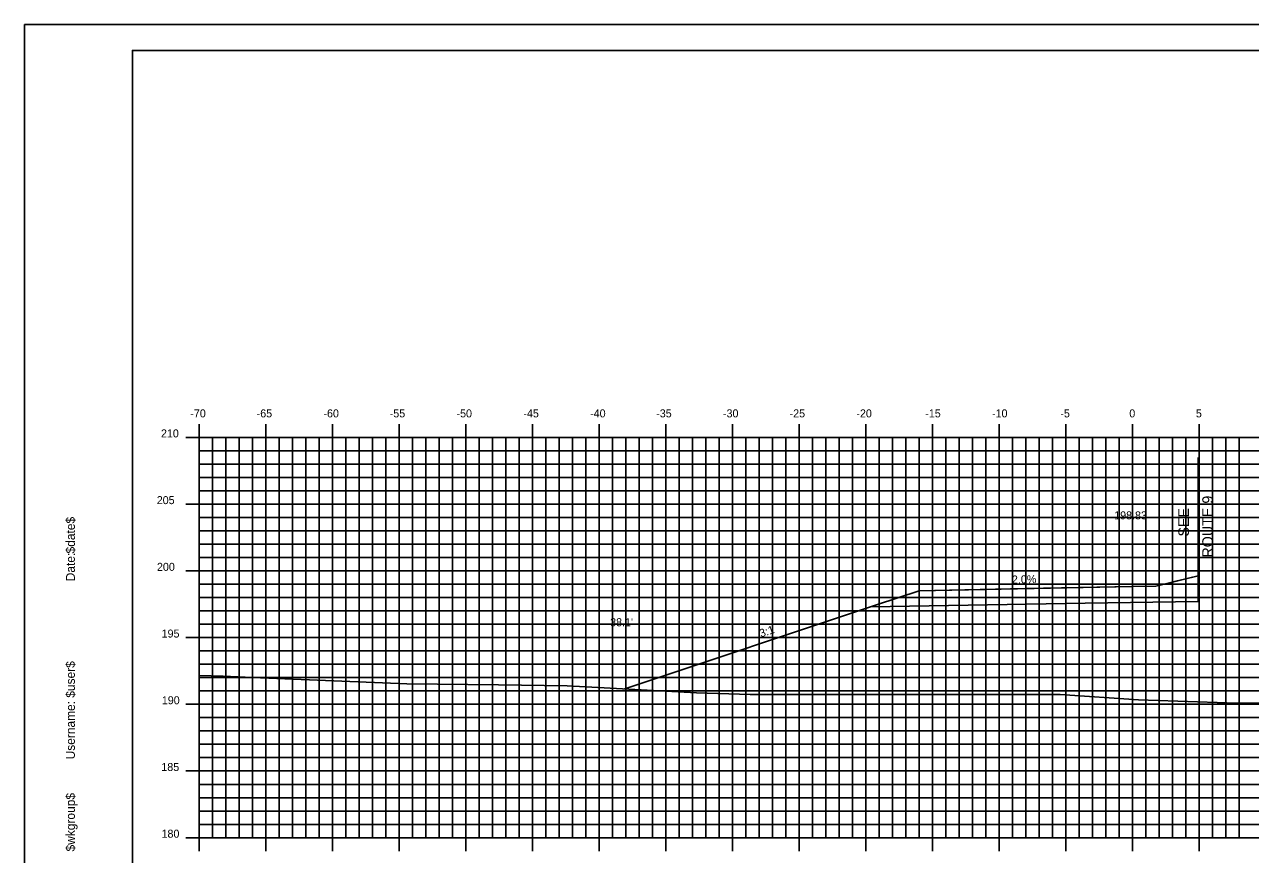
# Model space of a CAD drawing. Extents: x 1723321 to 1723493, y 458501 to 458611.
# Drawn here: x 1723320.9 to 1723412.9, y 458549 to 458611.2 of the extents above; entities that cross this region are included whole.
import ezdxf

# ---------------------------------------------------------------- set-up
doc = ezdxf.new("R2010")
doc.units = 0
for name, color, linetype in [('ANNOTATION', 7, 'Continuous'), ('BORDER', 7, 'Continuous'), ('D_Roadway_Centerline', 7, 'Continuous'), ('D_Roadway_Centerline_Text', 7, 'Continuous'), ('D_Roadway_Edge_Shoulder', 7, 'Continuous'), ('D_Roadway_SlopeLines', 7, 'Continuous'), ('D_Roadway_SubGrade', 7, 'Continuous'), ('D_Text_Standard', 7, 'Continuous'), ('H_V ANNOTATION', 7, 'Continuous'), ('MAJOR', 7, 'Continuous'), ('MINOR', 7, 'Continuous'), ('PLOT BOUNDARY', 7, 'Continuous'), ('S_Roadway_Centerline', 7, 'Continuous')]:
    doc.layers.add(name, color=color, linetype=linetype)

msp = doc.modelspace()

# ---------------------------------------------------------------- linework, layer by layer
msp.add_lwpolyline([(1723365.961, 458561.403), (1723384.837, 458567.696), (1723388.029, 458568.759), (1723396.029, 458568.919), (1723404.029, 458569.079), (1723405.784, 458569.114)])
at = {"layer": 'ANNOTATION'}
msp.add_line((1723400.476, 458567.821), (1723384.391, 458567.547), dxfattribs=at)
at = {"layer": 'BORDER'}
msp.add_lwpolyline([(1723329.029, 458504.254), (1723489.029, 458504.254), (1723489.029, 458609.254), (1723329.029, 458609.254)], close=True, dxfattribs=at)
at = {"layer": 'D_Roadway_Centerline'}
msp.add_lwpolyline([(1723405.784, 458569.114), (1723406.719, 458569.342), (1723407.412, 458569.511), (1723408.964, 458569.889)], dxfattribs=at)
at = {"layer": 'D_Roadway_Edge_Shoulder'}
msp.add_line((1723408.964, 458569.889), (1723408.964, 458569.639), dxfattribs=at)
msp.add_line((1723408.964, 458569.889), (1723408.964, 458569.639), dxfattribs=at)
at = {"layer": 'D_Roadway_SlopeLines'}
msp.add_line((1723388.029, 458568.759), (1723404.029, 458569.079), dxfattribs=at)
for points in [[(1723408.964, 458569.889), (1723405.784, 458569.114)], [(1723408.964, 458569.889), (1723405.784, 458569.114)], [(1723408.964, 458569.889), (1723405.784, 458569.114)], [(1723408.964, 458569.889), (1723405.784, 458569.114)], [(1723408.964, 458569.889), (1723405.784, 458569.114)], [(1723408.964, 458569.889), (1723405.784, 458569.114)], [(1723408.964, 458569.889), (1723405.784, 458569.114)], [(1723408.964, 458569.889), (1723405.784, 458569.114)], [(1723408.964, 458569.889), (1723405.784, 458569.114)], [(1723404.029, 458569.079), (1723405.784, 458569.114)], [(1723388.029, 458568.759), (1723384.837, 458567.696), (1723365.961, 458561.403)]]:
    msp.add_lwpolyline(points, dxfattribs=at)
at = {"layer": 'D_Roadway_SubGrade'}
msp.add_line((1723408.964, 458578.748), (1723408.964, 458567.966), dxfattribs=at)
for points in [[(1723405.784, 458569.114), (1723408.964, 458569.889), (1723408.964, 458569.639)], [(1723405.784, 458569.114), (1723408.964, 458569.889), (1723408.964, 458569.639)], [(1723405.784, 458569.114), (1723408.964, 458569.889), (1723408.964, 458569.639)], [(1723408.964, 458569.639), (1723408.964, 458569.889), (1723405.784, 458569.114)], [(1723400.476, 458567.821), (1723408.964, 458567.966)], [(1723408.964, 458567.966), (1723400.476, 458567.821)], [(1723408.964, 458567.966), (1723400.476, 458567.821)], [(1723408.964, 458567.966), (1723400.476, 458567.821)]]:
    msp.add_lwpolyline(points, dxfattribs=at)
at = {"layer": 'MAJOR'}
for p, q in [((1723334.029, 458581.256), (1723334.029, 458580.254)), ((1723339.029, 458581.256), (1723339.029, 458580.254)), ((1723344.029, 458581.256), (1723344.029, 458580.254)), ((1723349.029, 458581.256), (1723349.029, 458580.254)), ((1723354.029, 458581.256), (1723354.029, 458580.254)), ((1723359.029, 458581.256), (1723359.029, 458580.254)), ((1723364.029, 458581.256), (1723364.029, 458580.254)), ((1723369.029, 458581.256), (1723369.029, 458580.254)), ((1723374.029, 458581.256), (1723374.029, 458580.254)), ((1723379.029, 458581.256), (1723379.029, 458580.254)), ((1723384.029, 458581.256), (1723384.029, 458580.254)), ((1723389.029, 458581.256), (1723389.029, 458580.254)), ((1723394.029, 458581.256), (1723394.029, 458580.254)), ((1723399.029, 458581.256), (1723399.029, 458580.254)), ((1723404.029, 458581.256), (1723404.029, 458580.254)), ((1723409.029, 458581.256), (1723409.029, 458580.254)), ((1723333.027, 458580.254), (1723334.029, 458580.254)), ((1723334.029, 458580.254), (1723474.029, 458580.254)), ((1723334.029, 458550.254), (1723334.029, 458580.254)), ((1723334.029, 458550.254), (1723334.029, 458580.254)), ((1723334.029, 458580.254), (1723474.029, 458580.254)), ((1723339.029, 458550.254), (1723339.029, 458580.254)), ((1723344.029, 458550.254), (1723344.029, 458580.254)), ((1723349.029, 458550.254), (1723349.029, 458580.254)), ((1723354.029, 458550.254), (1723354.029, 458580.254)), ((1723359.029, 458550.254), (1723359.029, 458580.254)), ((1723364.029, 458550.254), (1723364.029, 458580.254)), ((1723369.029, 458550.254), (1723369.029, 458580.254)), ((1723374.029, 458550.254), (1723374.029, 458580.254)), ((1723379.029, 458550.254), (1723379.029, 458580.254)), ((1723384.029, 458550.254), (1723384.029, 458580.254)), ((1723389.029, 458550.254), (1723389.029, 458580.254)), ((1723394.029, 458550.254), (1723394.029, 458580.254)), ((1723399.029, 458550.254), (1723399.029, 458580.254)), ((1723404.029, 458550.254), (1723404.029, 458580.254)), ((1723409.029, 458550.254), (1723409.029, 458580.254)), ((1723333.027, 458575.254), (1723334.029, 458575.254)), ((1723334.029, 458575.254), (1723474.029, 458575.254)), ((1723333.027, 458570.254), (1723334.029, 458570.254)), ((1723334.029, 458570.254), (1723474.029, 458570.254)), ((1723333.027, 458565.254), (1723334.029, 458565.254)), ((1723334.029, 458565.254), (1723474.029, 458565.254)), ((1723333.027, 458560.254), (1723334.029, 458560.254)), ((1723334.029, 458560.254), (1723474.029, 458560.254)), ((1723333.027, 458555.254), (1723334.029, 458555.254)), ((1723334.029, 458555.254), (1723474.029, 458555.254)), ((1723333.027, 458550.254), (1723334.029, 458550.254)), ((1723334.029, 458550.254), (1723474.029, 458550.254)), ((1723334.029, 458550.254), (1723474.029, 458550.254)), ((1723334.029, 458549.252), (1723334.029, 458550.254)), ((1723339.029, 458549.252), (1723339.029, 458550.254)), ((1723344.029, 458549.252), (1723344.029, 458550.254)), ((1723349.029, 458549.252), (1723349.029, 458550.254)), ((1723354.029, 458549.252), (1723354.029, 458550.254)), ((1723359.029, 458549.252), (1723359.029, 458550.254)), ((1723364.029, 458549.252), (1723364.029, 458550.254)), ((1723369.029, 458549.252), (1723369.029, 458550.254)), ((1723374.029, 458549.252), (1723374.029, 458550.254)), ((1723379.029, 458549.252), (1723379.029, 458550.254)), ((1723384.029, 458549.252), (1723384.029, 458550.254)), ((1723389.029, 458549.252), (1723389.029, 458550.254)), ((1723394.029, 458549.252), (1723394.029, 458550.254)), ((1723399.029, 458549.252), (1723399.029, 458550.254)), ((1723404.029, 458549.252), (1723404.029, 458550.254)), ((1723409.029, 458549.252), (1723409.029, 458550.254))]:
    msp.add_line(p, q, dxfattribs=at)
at = {"layer": 'MINOR'}
for p, q in [((1723335.029, 458550.254), (1723335.029, 458580.254)), ((1723336.029, 458550.254), (1723336.029, 458580.254)), ((1723337.029, 458550.254), (1723337.029, 458580.254)), ((1723338.029, 458550.254), (1723338.029, 458580.254)), ((1723340.029, 458550.254), (1723340.029, 458580.254)), ((1723341.029, 458550.254), (1723341.029, 458580.254)), ((1723342.029, 458550.254), (1723342.029, 458580.254)), ((1723343.029, 458550.254), (1723343.029, 458580.254)), ((1723345.029, 458550.254), (1723345.029, 458580.254)), ((1723346.029, 458550.254), (1723346.029, 458580.254)), ((1723347.029, 458550.254), (1723347.029, 458580.254)), ((1723348.029, 458550.254), (1723348.029, 458580.254)), ((1723350.029, 458550.254), (1723350.029, 458580.254)), ((1723351.029, 458550.254), (1723351.029, 458580.254)), ((1723352.029, 458550.254), (1723352.029, 458580.254)), ((1723353.029, 458550.254), (1723353.029, 458580.254)), ((1723355.029, 458550.254), (1723355.029, 458580.254)), ((1723356.029, 458550.254), (1723356.029, 458580.254)), ((1723357.029, 458550.254), (1723357.029, 458580.254)), ((1723358.029, 458550.254), (1723358.029, 458580.254)), ((1723360.029, 458550.254), (1723360.029, 458580.254)), ((1723361.029, 458550.254), (1723361.029, 458580.254)), ((1723362.029, 458550.254), (1723362.029, 458580.254)), ((1723363.029, 458550.254), (1723363.029, 458580.254)), ((1723365.029, 458550.254), (1723365.029, 458580.254)), ((1723366.029, 458550.254), (1723366.029, 458580.254)), ((1723367.029, 458550.254), (1723367.029, 458580.254)), ((1723368.029, 458550.254), (1723368.029, 458580.254)), ((1723370.029, 458550.254), (1723370.029, 458580.254)), ((1723371.029, 458550.254), (1723371.029, 458580.254)), ((1723372.029, 458550.254), (1723372.029, 458580.254)), ((1723373.029, 458550.254), (1723373.029, 458580.254)), ((1723375.029, 458550.254), (1723375.029, 458580.254)), ((1723376.029, 458550.254), (1723376.029, 458580.254)), ((1723377.029, 458550.254), (1723377.029, 458580.254)), ((1723378.029, 458550.254), (1723378.029, 458580.254)), ((1723380.029, 458550.254), (1723380.029, 458580.254)), ((1723381.029, 458550.254), (1723381.029, 458580.254)), ((1723382.029, 458550.254), (1723382.029, 458580.254)), ((1723383.029, 458550.254), (1723383.029, 458580.254)), ((1723385.029, 458550.254), (1723385.029, 458580.254)), ((1723386.029, 458550.254), (1723386.029, 458580.254)), ((1723387.029, 458550.254), (1723387.029, 458580.254)), ((1723388.029, 458550.254), (1723388.029, 458580.254)), ((1723390.029, 458550.254), (1723390.029, 458580.254)), ((1723391.029, 458550.254), (1723391.029, 458580.254)), ((1723392.029, 458550.254), (1723392.029, 458580.254)), ((1723393.029, 458550.254), (1723393.029, 458580.254)), ((1723395.029, 458550.254), (1723395.029, 458580.254)), ((1723396.029, 458550.254), (1723396.029, 458580.254)), ((1723397.029, 458550.254), (1723397.029, 458580.254)), ((1723398.029, 458550.254), (1723398.029, 458580.254)), ((1723400.029, 458550.254), (1723400.029, 458580.254)), ((1723401.029, 458550.254), (1723401.029, 458580.254)), ((1723402.029, 458550.254), (1723402.029, 458580.254)), ((1723403.029, 458550.254), (1723403.029, 458580.254)), ((1723405.029, 458550.254), (1723405.029, 458580.254)), ((1723406.029, 458550.254), (1723406.029, 458580.254)), ((1723407.029, 458550.254), (1723407.029, 458580.254)), ((1723408.029, 458550.254), (1723408.029, 458580.254)), ((1723410.029, 458550.254), (1723410.029, 458580.254)), ((1723411.029, 458550.254), (1723411.029, 458580.254)), ((1723412.029, 458550.254), (1723412.029, 458580.254)), ((1723334.029, 458579.254), (1723474.029, 458579.254)), ((1723334.029, 458579.254), (1723335.031, 458579.254)), ((1723334.029, 458578.254), (1723474.029, 458578.254)), ((1723334.029, 458578.254), (1723335.031, 458578.254)), ((1723334.029, 458577.254), (1723474.029, 458577.254)), ((1723334.029, 458577.254), (1723335.031, 458577.254)), ((1723334.029, 458576.254), (1723474.029, 458576.254)), ((1723334.029, 458576.254), (1723335.031, 458576.254)), ((1723334.029, 458574.254), (1723474.029, 458574.254)), ((1723334.029, 458574.254), (1723335.031, 458574.254)), ((1723334.029, 458573.254), (1723474.029, 458573.254)), ((1723334.029, 458573.254), (1723335.031, 458573.254)), ((1723334.029, 458572.254), (1723474.029, 458572.254)), ((1723334.029, 458572.254), (1723335.031, 458572.254)), ((1723334.029, 458571.254), (1723474.029, 458571.254)), ((1723334.029, 458571.254), (1723335.031, 458571.254)), ((1723334.029, 458569.254), (1723474.029, 458569.254)), ((1723334.029, 458569.254), (1723335.031, 458569.254)), ((1723334.029, 458568.254), (1723474.029, 458568.254)), ((1723334.029, 458568.254), (1723335.031, 458568.254)), ((1723334.029, 458567.254), (1723474.029, 458567.254)), ((1723334.029, 458567.254), (1723335.031, 458567.254)), ((1723334.029, 458566.254), (1723474.029, 458566.254)), ((1723334.029, 458566.254), (1723335.031, 458566.254)), ((1723334.029, 458564.254), (1723474.029, 458564.254)), ((1723334.029, 458564.254), (1723335.031, 458564.254)), ((1723334.029, 458563.254), (1723474.029, 458563.254)), ((1723334.029, 458563.254), (1723335.031, 458563.254)), ((1723334.029, 458562.254), (1723474.029, 458562.254)), ((1723334.029, 458562.254), (1723335.031, 458562.254)), ((1723334.029, 458561.254), (1723474.029, 458561.254)), ((1723334.029, 458561.254), (1723335.031, 458561.254)), ((1723334.029, 458559.254), (1723474.029, 458559.254)), ((1723334.029, 458559.254), (1723335.031, 458559.254)), ((1723334.029, 458558.254), (1723474.029, 458558.254)), ((1723334.029, 458558.254), (1723335.031, 458558.254)), ((1723334.029, 458557.254), (1723474.029, 458557.254)), ((1723334.029, 458557.254), (1723335.031, 458557.254)), ((1723334.029, 458556.254), (1723474.029, 458556.254)), ((1723334.029, 458556.254), (1723335.031, 458556.254)), ((1723334.029, 458554.254), (1723474.029, 458554.254)), ((1723334.029, 458554.254), (1723335.031, 458554.254)), ((1723334.029, 458553.254), (1723474.029, 458553.254)), ((1723334.029, 458553.254), (1723335.031, 458553.254)), ((1723334.029, 458552.254), (1723474.029, 458552.254)), ((1723334.029, 458552.254), (1723335.031, 458552.254)), ((1723334.029, 458551.254), (1723474.029, 458551.254)), ((1723334.029, 458551.254), (1723335.031, 458551.254))]:
    msp.add_line(p, q, dxfattribs=at)
at = {"layer": 'PLOT BOUNDARY'}
msp.add_lwpolyline([(1723320.936, 458501.195), (1723490.936, 458501.195), (1723490.936, 458611.195), (1723320.936, 458611.195)], close=True, dxfattribs=at)
at = {"layer": 'S_Roadway_Centerline'}
msp.add_lwpolyline([(1723334.029, 458562.416), (1723335.834, 458562.354), (1723338.025, 458562.255), (1723349.598, 458561.79), (1723356.493, 458561.701), (1723361.621, 458561.642), (1723371.34, 458561.107), (1723375.346, 458560.975), (1723380.963, 458560.978), (1723398.602, 458560.98), (1723404.466, 458560.596), (1723411.856, 458560.327), (1723422.097, 458560.488), (1723431.206, 458559.748), (1723437.19, 458559.453), (1723445.206, 458559.48), (1723450.944, 458559.196), (1723457.969, 458559.095), (1723469.498, 458558.688), (1723470.086, 458558.662), (1723471.145, 458558.626), (1723474.029, 458558.512)], dxfattribs=at)

# ---------------------------------------------------------------- texts
at = {"layer": 'ANNOTATION'}
for s, height, rotation, p in [('ROUTE 9', 0.8, 90, (1723410.062, 458571.248)), ('SEE', 0.8, 90, (1723408.262, 458572.823)), ('2.0%', 0.6, 1.14576, (1723394.992, 458569.299)), ('3:1', 0.6, 18.43495, (1723376.164, 458565.259))]:
    msp.add_text(s, height=height, rotation=rotation, dxfattribs=at).set_placement(p)
at = {"layer": 'BORDER'}
for s, p in [('$date$', (1723324.714, 458571.559)), ('Date:', (1723324.714, 458569.471)), ('$user$', (1723324.714, 458560.746)), ('Username:', (1723324.714, 458556.122)), ('$wkgroup$', (1723324.714, 458549.224))]:
    msp.add_text(s, height=0.6696, rotation=90, dxfattribs=at).set_placement(p)
at = {"layer": 'D_Roadway_Centerline_Text'}
msp.add_text('198.83', height=0.6, dxfattribs=at).set_placement((1723402.656, 458574.111))
at = {"layer": 'D_Text_Standard'}
msp.add_text("38.1'", height=0.6, dxfattribs=at).set_placement((1723364.856, 458566.103))
at = {"layer": 'H_V ANNOTATION'}
for s, p in [('-70', (1723333.37, 458581.754)), ('-65', (1723338.346, 458581.754)), ('-60', (1723343.354, 458581.754)), ('-55', (1723348.325, 458581.754)), ('-50', (1723353.333, 458581.754)), ('-45', (1723358.346, 458581.754)), ('-40', (1723363.354, 458581.754)), ('-35', (1723368.309, 458581.754)), ('-30', (1723373.317, 458581.754)), ('-25', (1723378.314, 458581.754)), ('-20', (1723383.322, 458581.754)), ('-15', (1723388.486, 458581.754)), ('-10', (1723393.494, 458581.754)), ('-5', (1723398.619, 458581.754)), ('0', (1723403.788, 458581.754)), ('5', (1723408.78, 458581.754)), ('210', (1723331.169, 458580.254)), ('205', (1723330.853, 458575.254)), ('200', (1723330.869, 458570.254)), ('195', (1723331.218, 458565.254)), ('190', (1723331.234, 458560.254)), ('185', (1723331.196, 458555.254)), ('180', (1723331.212, 458550.254))]:
    msp.add_text(s, height=0.6, dxfattribs=at).set_placement(p)
at = {"layer": 'MAJOR'}
msp.add_text('-', height=0.006, dxfattribs=at).set_placement((1723334.024, 458550.254))

doc.saveas('drawing.dxf')
